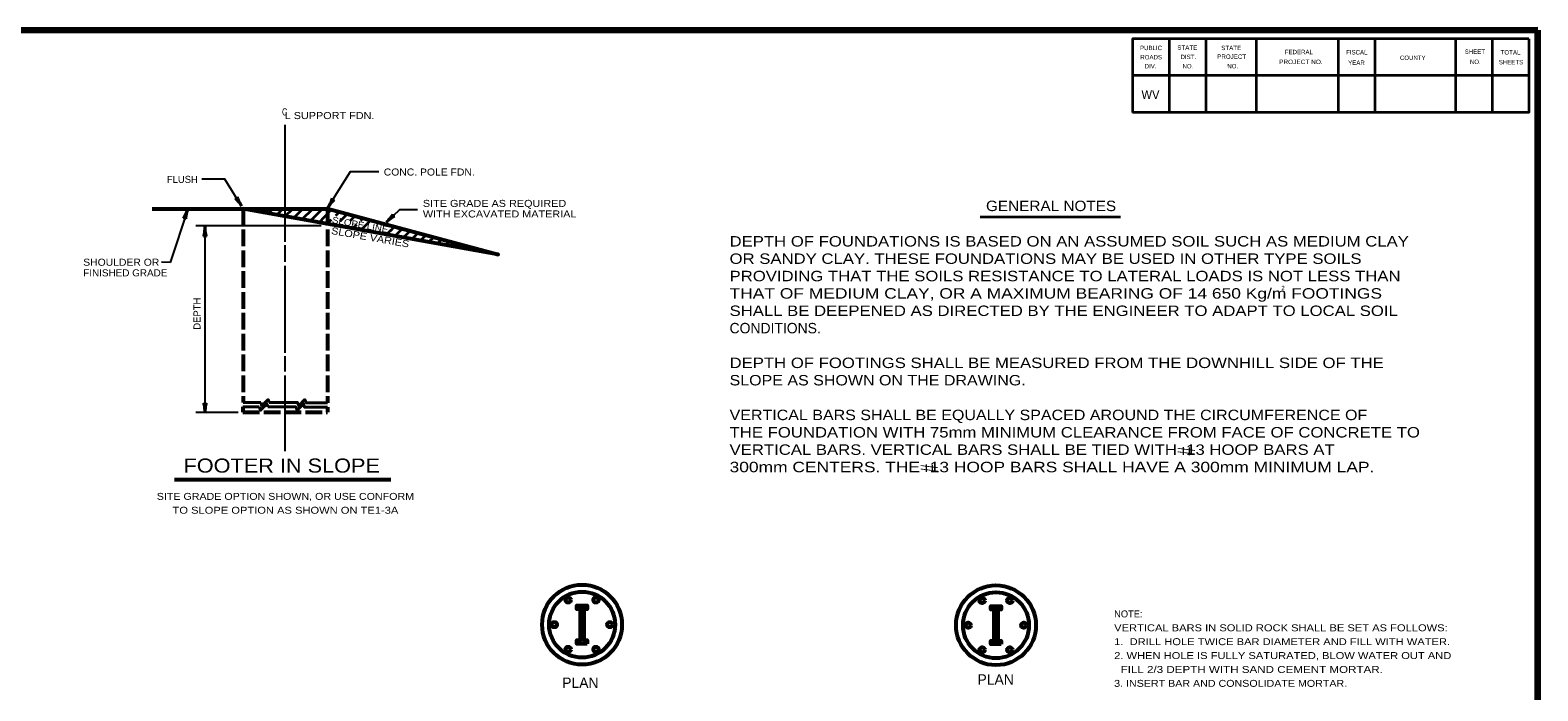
# Model space of a CAD drawing. Extents: x -27 to 828, y -12 to 532.
# Drawn here: x 300 to 822, y 297 to 525 of the extents above; entities that cross this region are included whole.
import ezdxf
from ezdxf.enums import TextEntityAlignment as Align

# ---------------------------------------------------------------- set-up
doc = ezdxf.new("R2010")
doc.units = 0
doc.header["$LTSCALE"] = 0.96
doc.linetypes.add('LONG_DASHED', pattern=[7.5, 6, -1.5])
doc.layers.add('1', color=7, linetype='Continuous', lineweight=35)
doc.layers.add('61', color=7, linetype='Continuous', lineweight=35)

msp = doc.modelspace()

# ---------------------------------------------------------------- linework, layer by layer
at = {"layer": '1', "lineweight": 158}
msp.add_line((821.9567, -0.9312), (821.9567, 525.1688), dxfattribs=at)
at = {"layer": '1', "lineweight": 13}
msp.add_line((821.9567, -0.9312), (821.9567, 525.1688), dxfattribs=at)
at = {"layer": '1', "lineweight": 25}
for p, q in [((388.7089, 452.0356), (388.7089, 492.4996)), ((354.9649, 463.3156), (348.9169, 444.9316)), ((357.7729, 457.6516), (401.0929, 457.6516)), ((360.9169, 457.4356), (360.9169, 392.8516)), ((388.7089, 445.1476), (388.7089, 450.9076)), ((348.9169, 444.9316), (345.8689, 444.9556)), ((388.7089, 413.6596), (388.7089, 443.7796)), ((388.7089, 407.2036), (388.7089, 412.5076)), ((388.7089, 379.6276), (388.7089, 405.8356)), ((372.4129, 393.0916), (357.7729, 393.0916))]:
    msp.add_line(p, q, dxfattribs=at)
at = {"layer": '1', "lineweight": 53}
for p, q in [((342.6289, 463.4836), (403.4929, 463.4836)), ((350.3569, 369.9076), (425.1889, 369.9076)), ((491.9639, 324.4877), (490.1306, 326.321)), ((493.1639, 325.8333), (492.6762, 326.321)), ((635.1349, 324.2939), (633.3016, 326.1272)), ((636.3349, 325.6395), (635.8472, 326.1272)), ((491.9639, 321.9421), (490.7639, 323.1421)), ((491.9639, 319.3965), (490.7639, 320.5965)), ((635.1349, 321.7483), (633.9349, 322.9483)), ((635.1349, 319.2027), (633.9349, 320.4027)), ((490.6027, 313.121), (489.5639, 314.1598)), ((491.9639, 316.8509), (490.7639, 318.0509)), ((493.1482, 313.121), (490.7639, 315.5053)), ((633.7737, 312.9272), (632.7349, 313.966)), ((635.1349, 316.6571), (633.9349, 317.8571)), ((636.3192, 312.9272), (633.9349, 315.3115))]:
    msp.add_line(p, q, dxfattribs=at)
at = {"layer": '1', "linetype": 'LONG_DASHED', "lineweight": 53}
for p, q in [((374.0929, 463.4836), (374.0929, 396.5476)), ((403.3249, 463.4836), (403.3249, 396.4036)), ((374.0689, 394.9876), (374.0689, 393.1156)), ((374.0689, 393.1156), (403.3009, 393.1156)), ((403.3009, 394.8436), (403.3009, 393.1156))]:
    msp.add_line(p, q, dxfattribs=at)
at = {"layer": '1'}
for p, q in [((379.9009, 462.4516), (380.9329, 463.4836)), ((382.8289, 461.9236), (384.3889, 463.4836)), ((385.7569, 461.3716), (387.8209, 463.4836)), ((388.6849, 460.8676), (391.2769, 463.4836)), ((391.6129, 460.3396), (394.7329, 463.4836)), ((394.5169, 459.8356), (398.1889, 463.4836)), ((397.4449, 459.3076), (401.6209, 463.4836)), ((400.3729, 458.7556), (404.7409, 463.1476)), ((403.3009, 458.2516), (404.7409, 459.7156)), ((406.1329, 461.0836), (407.4769, 462.4276)), ((407.6449, 459.1396), (410.1889, 461.6836)), ((411.3169, 459.3796), (412.9009, 460.9636)), ((414.7969, 459.4276), (415.6129, 460.2196)), ((414.9889, 456.1636), (418.3249, 459.4996)), ((629.059, 460.6265), (677.572, 460.6265)), ((406.2289, 457.7236), (406.7569, 458.2516)), ((409.1569, 457.2196), (409.3489, 457.4116)), ((412.0609, 456.6916), (413.4049, 457.9876)), ((417.9169, 455.6356), (418.1329, 455.8756)), ((420.4849, 458.2036), (421.0609, 458.7556)), ((420.8449, 455.1076), (421.3489, 455.6116)), ((423.4849, 457.7476), (423.7729, 458.0356)), ((423.7729, 454.6036), (425.3569, 456.1636)), ((425.0689, 455.8756), (426.5089, 457.3156)), ((426.7009, 454.0756), (429.2209, 456.5956)), ((429.6289, 453.5476), (431.9329, 455.8756)), ((432.5569, 453.0436), (434.6689, 455.1316)), ((435.4849, 452.4916), (437.3809, 454.3876)), ((438.4129, 451.9876), (440.1169, 453.6676)), ((441.3409, 451.4596), (442.8049, 452.9476)), ((444.2689, 450.9316), (445.5409, 452.2036)), ((447.1969, 450.4276), (448.2529, 451.4836)), ((450.1249, 449.8996), (450.9649, 450.7636)), ((453.0529, 449.3476), (453.7009, 450.0436))]:
    msp.add_line(p, q, dxfattribs=at)
at = {"layer": '1', "lineweight": 40}
for p, q in [((374.0929, 396.5476), (380.2369, 396.5476)), ((374.0689, 394.9876), (379.7089, 394.9876))]:
    msp.add_line(p, q, dxfattribs=at)
at = {"layer": '1', "lineweight": 158}
msp.add_lwpolyline([(821.9567, 525.1688), (30.2567, 525.0688), (30.3567, -0.9312)], dxfattribs=at)
at = {"layer": '1', "lineweight": 25}
for points in [[(403.4449, 463.8676), (411.2689, 476.2756), (421.0129, 476.2756)], [(373.5889, 464.3236), (367.8289, 473.7316), (359.7889, 473.7316)], [(423.6769, 458.8276), (428.2849, 463.1716), (434.3809, 463.1716)]]:
    msp.add_lwpolyline(points, dxfattribs=at)
at = {"layer": '1', "lineweight": 53}
msp.add_lwpolyline([(403.4929, 463.4836), (462.3889, 447.6916), (374.0929, 463.4836)], dxfattribs=at)
at = {"layer": '1', "lineweight": 40}
for points in [[(380.2369, 396.5476), (380.6449, 395.3956), (382.8049, 397.5316), (383.1649, 396.5476)], [(383.1649, 396.5476), (392.9089, 396.5476), (393.3409, 395.3956), (395.5009, 397.5316), (395.9089, 396.4036), (403.3249, 396.4036)], [(379.7089, 394.9876), (380.1409, 393.8356), (382.2769, 395.9956), (382.6609, 394.9876)], [(382.6609, 394.9876), (392.4049, 394.9876), (392.8129, 393.8356), (394.9729, 395.9956), (395.4049, 394.8436), (403.3009, 394.8436)]]:
    msp.add_lwpolyline(points, dxfattribs=at)
at = {"layer": '1', "lineweight": 53}
for points in [[(493.1639, 313.121), (489.5639, 313.121), (489.5639, 314.321), (490.7639, 314.321), (490.7639, 325.121), (489.5639, 325.121), (489.5639, 326.321), (493.1639, 326.321), (493.1639, 325.121), (491.9639, 325.121), (491.9639, 314.321), (493.1639, 314.321)], [(636.3349, 312.9272), (632.7349, 312.9272), (632.7349, 314.1272), (633.9349, 314.1272), (633.9349, 324.9272), (632.7349, 324.9272), (632.7349, 326.1272), (636.3349, 326.1272), (636.3349, 324.9272), (635.1349, 324.9272), (635.1349, 314.1272), (636.3349, 314.1272)]]:
    msp.add_lwpolyline(points, close=True, dxfattribs=at)
for centre, radius in [((491.3639, 319.721), 13.8), ((491.3639, 319.721), 11.4), ((486.5639, 328.2612), 0.9), ((496.1639, 328.2612), 0.9), ((634.5349, 319.5272), 13.8), ((634.5349, 319.5272), 11.4), ((629.7349, 328.0674), 0.9), ((639.3349, 328.0674), 0.9), ((481.7639, 319.721), 0.9), ((500.9639, 319.721), 0.9), ((624.9349, 319.5272), 0.9), ((644.1349, 319.5272), 0.9), ((486.5639, 311.1808), 0.9), ((496.1639, 311.1808), 0.9), ((629.7349, 310.987), 0.9), ((639.3349, 310.987), 0.9)]:
    msp.add_circle(centre, radius, dxfattribs=at)
at = {"layer": '1', "lineweight": 40}
for centre, major_axis, ratio, start_param, end_param in [((372.5981, 465.292), (1.2961, -1.7598), 0.122415, 0.89635335, 3.14159265), ((372.5981, 465.292), (1.2961, -1.7598), 0.122415, 0.89635335, 3.14159265), ((373.0874, 465.6322), (-0.9321, 1.94), 0.07063, 6.28230741, 8.55970261), ((373.0874, 465.6322), (-0.9321, 1.94), 0.07063, 6.28230741, 8.55970261), ((403.8793, 465.1772), (-0.999, -1.9439), 0.122415, 0.89635335, 3.14159265), ((404.4018, 464.8905), (1.3223, 1.6982), 0.07063, 6.28230741, 8.55970261), ((354.303, 462.0981), (-0.8723, -1.9676), 0.07063, 6.28230741, 8.55970261), ((354.8793, 461.9463), (0.4991, 2.1278), 0.122415, 0.89635335, 3.14159265), ((424.4126, 459.9763), (-1.4474, -1.6376), 0.122415, 0.89635335, 3.14159265), ((424.8482, 459.5696), (-1.7001, -1.3198), 0.07063, 3.14071475, 5.41810995), ((360.668, 456.0705), (-0.2142, -2.1416), 0.07063, 6.28230741, 8.55970261), ((361.2629, 456.1063), (-0.1904, 2.1773), 0.122415, 0.89635335, 3.14159265), ((360.5891, 394.1746), (0.1904, -2.1773), 0.122415, 0.89635335, 3.14159265), ((361.184, 394.2103), (0.2142, 2.1416), 0.07063, 6.28230741, 8.55970261)]:
    msp.add_ellipse(centre, major_axis=major_axis, ratio=ratio, start_param=start_param, end_param=end_param, dxfattribs=at)
at = {"layer": '61'}
for p, q in [((694.4567, 522.1688), (694.4567, 496.7688)), ((707.1567, 522.1688), (707.1567, 496.7688)), ((724.5567, 522.1688), (724.5567, 496.7688)), ((752.8567, 522.1688), (752.8567, 496.7688)), ((765.5567, 522.1688), (765.5567, 496.7688)), ((793.4567, 522.1688), (793.4567, 496.7688)), ((806.1567, 522.1688), (806.1567, 496.7688)), ((818.8567, 509.4688), (681.7567, 509.4688))]:
    msp.add_line(p, q, dxfattribs=at)
for points in [[(818.8567, 522.1688), (681.7567, 522.1688), (681.7567, 496.7688)], [(818.8567, 522.1688), (818.8567, 496.7688), (681.7567, 496.7688)]]:
    msp.add_lwpolyline(points, dxfattribs=at)

# ---------------------------------------------------------------- texts
at = {"layer": '1'}
for s, height, width, p in [('WV', 3.048, 0.95, (684.8567, 501.3688)), ('C', 2.438, 0.75, (387.5809, 495.7156)), ('L SUPPORT FDN.', 2.438, 1.15, (388.4929, 494.4436)), ('CONC. POLE FDN.', 2.438, 1.1, (422.7649, 474.9316)), ('SITE GRADE AS REQUIRED', 2.438, 1.15, (436.3009, 464.0836)), ('GENERAL NOTES', 3.6, 1.1, (631.0748, 462.6429)), ('WITH EXCAVATED MATERIAL', 2.438, 1.15, (436.3009, 460.4356)), ('DEPTH OF FOUNDATIONS IS BASED ON AN ASSUMED SOIL SUCH AS MEDIUM CLAY', 3.6, 1.2, (542.3819, 450.4012)), ('SHOULDER OR', 2.438, 1.1, (318.8209, 443.7556)), ('OR SANDY CLAY. THESE FOUNDATIONS MAY BE USED IN OTHER TYPE SOILS', 3.6, 1.2, (542.3819, 444.4012)), ('FINISHED GRADE', 2.438, 1.05, (318.8209, 440.0836)), ('PROVIDING THAT THE SOILS RESISTANCE TO LATERAL LOADS IS NOT LESS THAN', 3.6, 1.2, (542.3819, 438.4012)), ('THAT OF MEDIUM CLAY, OR A MAXIMUM BEARING OF 14 650 Kg/m FOOTINGS', 3.6, 1.25, (542.3819, 432.4012)), ('SHALL BE DEEPENED AS DIRECTED BY THE ENGINEER TO ADAPT TO LOCAL SOIL', 3.6, 1.2, (542.3819, 426.4012)), ('DEPTH OF FOOTINGS SHALL BE MEASURED FROM THE DOWNHILL SIDE OF THE', 3.6, 1.2, (542.3819, 408.4012)), ('SLOPE AS SHOWN ON THE DRAWING.', 3.6, 1.15, (542.3819, 402.4012)), ('VERTICAL BARS SHALL BE EQUALLY SPACED AROUND THE CIRCUMFERENCE OF', 3.6, 1.15, (542.3819, 390.4012)), ('THE FOUNDATION WITH 75mm MINIMUM CLEARANCE FROM FACE OF CONCRETE TO', 3.6, 1.2, (542.3819, 384.4012)), ('VERTICAL BARS. VERTICAL BARS SHALL BE TIED WITH  13 HOOP BARS AT', 3.6, 1.2, (542.3819, 378.4012)), ('300mm CENTERS. THE  13 HOOP BARS SHALL HAVE A 300mm MINIMUM LAP.', 3.6, 1.25, (542.3819, 372.4012)), ('VERTICAL BARS IN SOLID ROCK SHALL BE SET AS FOLLOWS:', 2.4, 1.2, (675.4084, 317.434)), ('1.  DRILL HOLE TWICE BAR DIAMETER AND FILL WITH WATER.', 2.4, 1.2, (675.4084, 312.634)), ('2. WHEN HOLE IS FULLY SATURATED, BLOW WATER OUT AND', 2.4, 1.2, (675.4084, 307.834)), ('  FILL 2/3 DEPTH WITH SAND CEMENT MORTAR.', 2.4, 1.25, (675.4084, 303.034)), ('3. INSERT BAR AND CONSOLIDATE MORTAR.', 2.4, 1.15, (675.4084, 298.234))]:
    msp.add_text(s, height=height, dxfattribs=dict(at, width=width)).set_placement(p)
msp.add_text('FLUSH', height=2.438, dxfattribs=at).set_placement((358.4399, 472.3876), align=Align.RIGHT)
at = {"layer": '1', "width": 1.15}
for s, height, p in [('SLOPE LINE', 2.194, (414.4461, 456.8579)), ('SLOPE VARIES', 2.438, (417.8754, 452.3865))]:
    msp.add_text(s, height=height, rotation=350, dxfattribs=at).set_placement(p, align=Align.CENTER)
at = {"layer": '1'}
for s, height, width, p in [('2', 1.5, 0.9, (733.8367, 435.3256)), ('FOOTER IN SLOPE', 4.877, 1.15, (387.4755, 372.2596)), ('SITE GRADE OPTION SHOWN, OR USE CONFORM', 2.4, 1.15, (388.7535, 362.8544)), ('TO SLOPE OPTION AS SHOWN ON TE1-3A', 2.4, 1.2, (388.7536, 358.0544))]:
    msp.add_text(s, height=height, dxfattribs=dict(at, width=width)).set_placement(p, align=Align.CENTER)
msp.add_text('DEPTH', height=2.438, rotation=90, dxfattribs=at).set_placement((359.3809, 427.1888), align=Align.CENTER)
for s, height, p in [('CONDITIONS.', 3.6, (542.3819, 420.4012)), ('NOTE:', 2.4, (675.4084, 322.234)), ('PLAN', 3.6, (628.1203, 298.9692)), ('PLAN', 3.6, (484.4829, 297.8423))]:
    msp.add_text(s, height=height, dxfattribs=at).set_placement(p)
at = {"layer": '1', "width": 0.65}
for p in [(703.3428, 378.2498), (614.4558, 372.2964)]:
    msp.add_text('#', height=6, rotation=90, dxfattribs=at).set_placement(p)
at = {"layer": '61'}
for s, height, rotation, p in [('PUBLIC', 1.525, 0.033, (684.3567, 518.2688)), ('ROADS', 1.525, 0.124, (684.4567, 515.0688)), ('DIST.', 1.525, 0.056, (698.3567, 515.1688)), ('FEDERAL', 1.523, 0.007, (734.4567, 516.8688)), ('FISCAL', 1.525, 359.942, (755.6567, 516.7688)), ('COUNTY', 1.523, 0.069, (774.2567, 514.8688)), ('SHEET', 1.525, 0.059, (796.6567, 516.9688)), ('DIV.', 1.525, 359.932, (685.9567, 511.9688)), ('YEAR', 1.523, 0.105, (756.3567, 513.1688)), ('SHEETS', 1.523, 359.959, (808.4567, 513.3688))]:
    msp.add_text(s, height=height, rotation=rotation, dxfattribs=at).set_placement(p)
for s, rotation, width, p in [('STATE', 0.059, 1.05, (697.2567, 518.3688)), ('PROJECT', 359.908, 1.05, (711.0567, 515.2688)), ('STATE', 0.059, 1.05, (712.4567, 518.2688)), ('TOTAL', 359.926, 1.05, (809.0567, 516.7688)), ('NO.', 359.852, 0.9, (699.0567, 511.9688)), ('NO.', 0.225, 0.9, (714.5567, 511.9688)), ('PROJECT NO.', 359.922, 1.1, (732.4567, 513.4688)), ('NO.', 359.852, 0.9, (798.4567, 513.4688))]:
    msp.add_text(s, height=1.525, rotation=rotation, dxfattribs=dict(at, width=width)).set_placement(p)

doc.saveas('drawing.dxf')
